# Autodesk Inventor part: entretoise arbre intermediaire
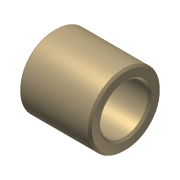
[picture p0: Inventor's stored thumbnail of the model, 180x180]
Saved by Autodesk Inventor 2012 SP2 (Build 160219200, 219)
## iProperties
Created: 2013-04
Part Number: entretoise arbre intermediaire
Material: Default
Document SubType Name: Modeling
Designer: papa
Density: 1 g/cm^3
Mass: 2.5183 g
Surface Area: 19.2211 cm^2
Volume: 2.5183 cm^3
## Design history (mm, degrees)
node "entretoise arbre intermediaire1"
node "entretoise arbre intermediaire"
node "Base1"
